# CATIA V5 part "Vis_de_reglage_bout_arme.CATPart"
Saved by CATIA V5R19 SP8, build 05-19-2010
Part number: Vis_de_reglage_bout_arme
Bounding box of the stored display mesh (mm): x -81.435 to -50, y -610.988 to -590.988, z 1340.785 to 1358.106
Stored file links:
  G:\EU_thinkMotion\CFAO_2010\MMS_groupe2\MMS_groupe2\OK\nrosalie\nrosalie_cfao_support_d_arme_legere_final\Vis_de_reglage_bout_arme.CATPart
  G:\EU_thinkMotion\CFAO_2010\MMS_groupe2\MMS_groupe2\OK\nrosalie\nrosalie_cfao_support_d_arme_legere_final\nrosalie_Support_d_arme_legere.CATProduct
  G:\EU_thinkMotion\CFAO_2010\MMS_groupe2\MMS_groupe2\OK\nrosalie\nrosalie_cfao_support_d_arme_legere_final\Bras.CATPart
  G:\EU_thinkMotion\CFAO_2010\MMS_groupe2\MMS_groupe2\OK\nrosalie\nrosalie_cfao_support_d_arme_legere_final\Arme.CATPart
  G:\EU_thinkMotion\CFAO_2010\MMS_groupe2\MMS_groupe2\OK\nrosalie\nrosalie_cfao_support_d_arme_legere_final\Squelette_bras.CATPart
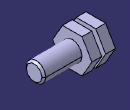
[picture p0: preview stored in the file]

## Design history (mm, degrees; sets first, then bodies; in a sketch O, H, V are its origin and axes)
Set1
  Sketch1 on face of DatumSurface1, origin (-69.4353, 0, 0), H (0, -1, 0), V (0, 0, 1)
    projected circle E1 centre (600.9884, 1349.4457) radius 5 from edge of DatumCurve1
Set2
  DatumSurface1: linked copy from another document
  DatumCurve1: linked copy from another document
  DatumSurface2: linked copy from another document
  Point1: linked copy from another document
Body1 (main body)
  Pad1: profile Sketch1, direction (1, 0, 0), up to face of DatumSurface2, opposite side length 7
  Chamfer1: length 1, angle 45, on edge [end face of Pad1 | face of Pad1 from Sketch1.E1]
  Sketch2 on start face of Pad1, origin (-76.4353, 0, 0), H (0, -1, 0), V (0, 0, 1)
    construction circle A1 centre (605.2221, 1347.9638) radius 0
    line L1 (600.9884, 1349.4457) -> (600.9884, 1349.4457)
    line L2 (600.9884, 1349.4457) -> (600.9884, 1349.4457)
    line L3 (600.9884, 1349.4457) -> (600.9884, 1349.4457)
    line L4 (600.9884, 1349.4457) -> (600.9884, 1349.4457)
    line L5 (600.9884, 1349.4457) -> (600.9884, 1349.4457)
    line L6 (600.9884, 1349.4457) -> (600.9884, 1349.4457)
    construction line L7 (578.8228, 1349.4457) -> (639.7556, 1349.4457)
    construction circle A2 centre (600.9884, 1349.4457) radius 0
    line L8 (600.9884, 1349.4457) -> (600.9884, 1349.4457)
    line L9 (600.9884, 1349.4457) -> (600.9884, 1349.4457)
    line L10 (600.9884, 1349.4457) -> (600.9884, 1349.4457)
    line L11 (600.9884, 1349.4457) -> (600.9884, 1349.4457)
    line L12 (600.9884, 1349.4457) -> (600.9884, 1349.4457)
    line L13 (600.9884, 1349.4457) -> (600.9884, 1349.4457)
    construction circle A3 centre (600.9884, 1349.4457) radius 10
    point P19 (600.9884, 1349.4457)
    line L14 (595.9884, 1358.106) -> (605.9884, 1358.106)
    point P20 (595.9884, 1358.106)
    point P21 (605.9884, 1358.106)
    line L15 (605.9884, 1358.106) -> (610.9884, 1349.4457)
    point P22 (610.9884, 1349.4457)
    line L16 (610.9884, 1349.4457) -> (605.9884, 1340.7855)
    point P23 (605.9884, 1340.7855)
    line L17 (605.9884, 1340.7855) -> (595.9884, 1340.7855)
    point P24 (595.9884, 1340.7855)
    line L18 (595.9884, 1340.7855) -> (590.9884, 1349.4457)
    point P25 (590.9884, 1349.4457)
    line L19 (590.9884, 1349.4457) -> (595.9884, 1358.106)
    point P26 (595.9884, 1358.106)
    axis line L20 (600.9884, 1349.4457) -> (610.038, 1365.12)
    reference projected circle E1 centre (600.9884, 1349.4457) radius 5 from edge [face of Pad1 from Sketch1.E1 | start face of Pad1]
    angle L20 L7 = 60
    radius A3 = 10
    horizontal: L7 H, L14 H
    coincidence: P20 P26, P22 L7, P23 A3, P24 A3, P21 A3, P20 A3, P25 A3, P22 A3, P25 L7, P21 L20, L7 P19
    symmetry: L14 L17 L7
    concentricity: A3 E1
  Pad2: profile Sketch2, direction (-1, 0, 0), length 5
  Sketch3 on face of DatumSurface1, origin (-69.4353, 0, 0), H (0, -1, 0), V (0, 0, 1)
    circle A1 centre (600.9884, 1349.4457) radius 5
    reference projected circle E2 centre (600.9884, 1349.4457) radius 5 from edge of DatumCurve1
    coincidence: A1 E2
  Pad3: profile Sketch3, direction (-1, 0, 0), length 5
